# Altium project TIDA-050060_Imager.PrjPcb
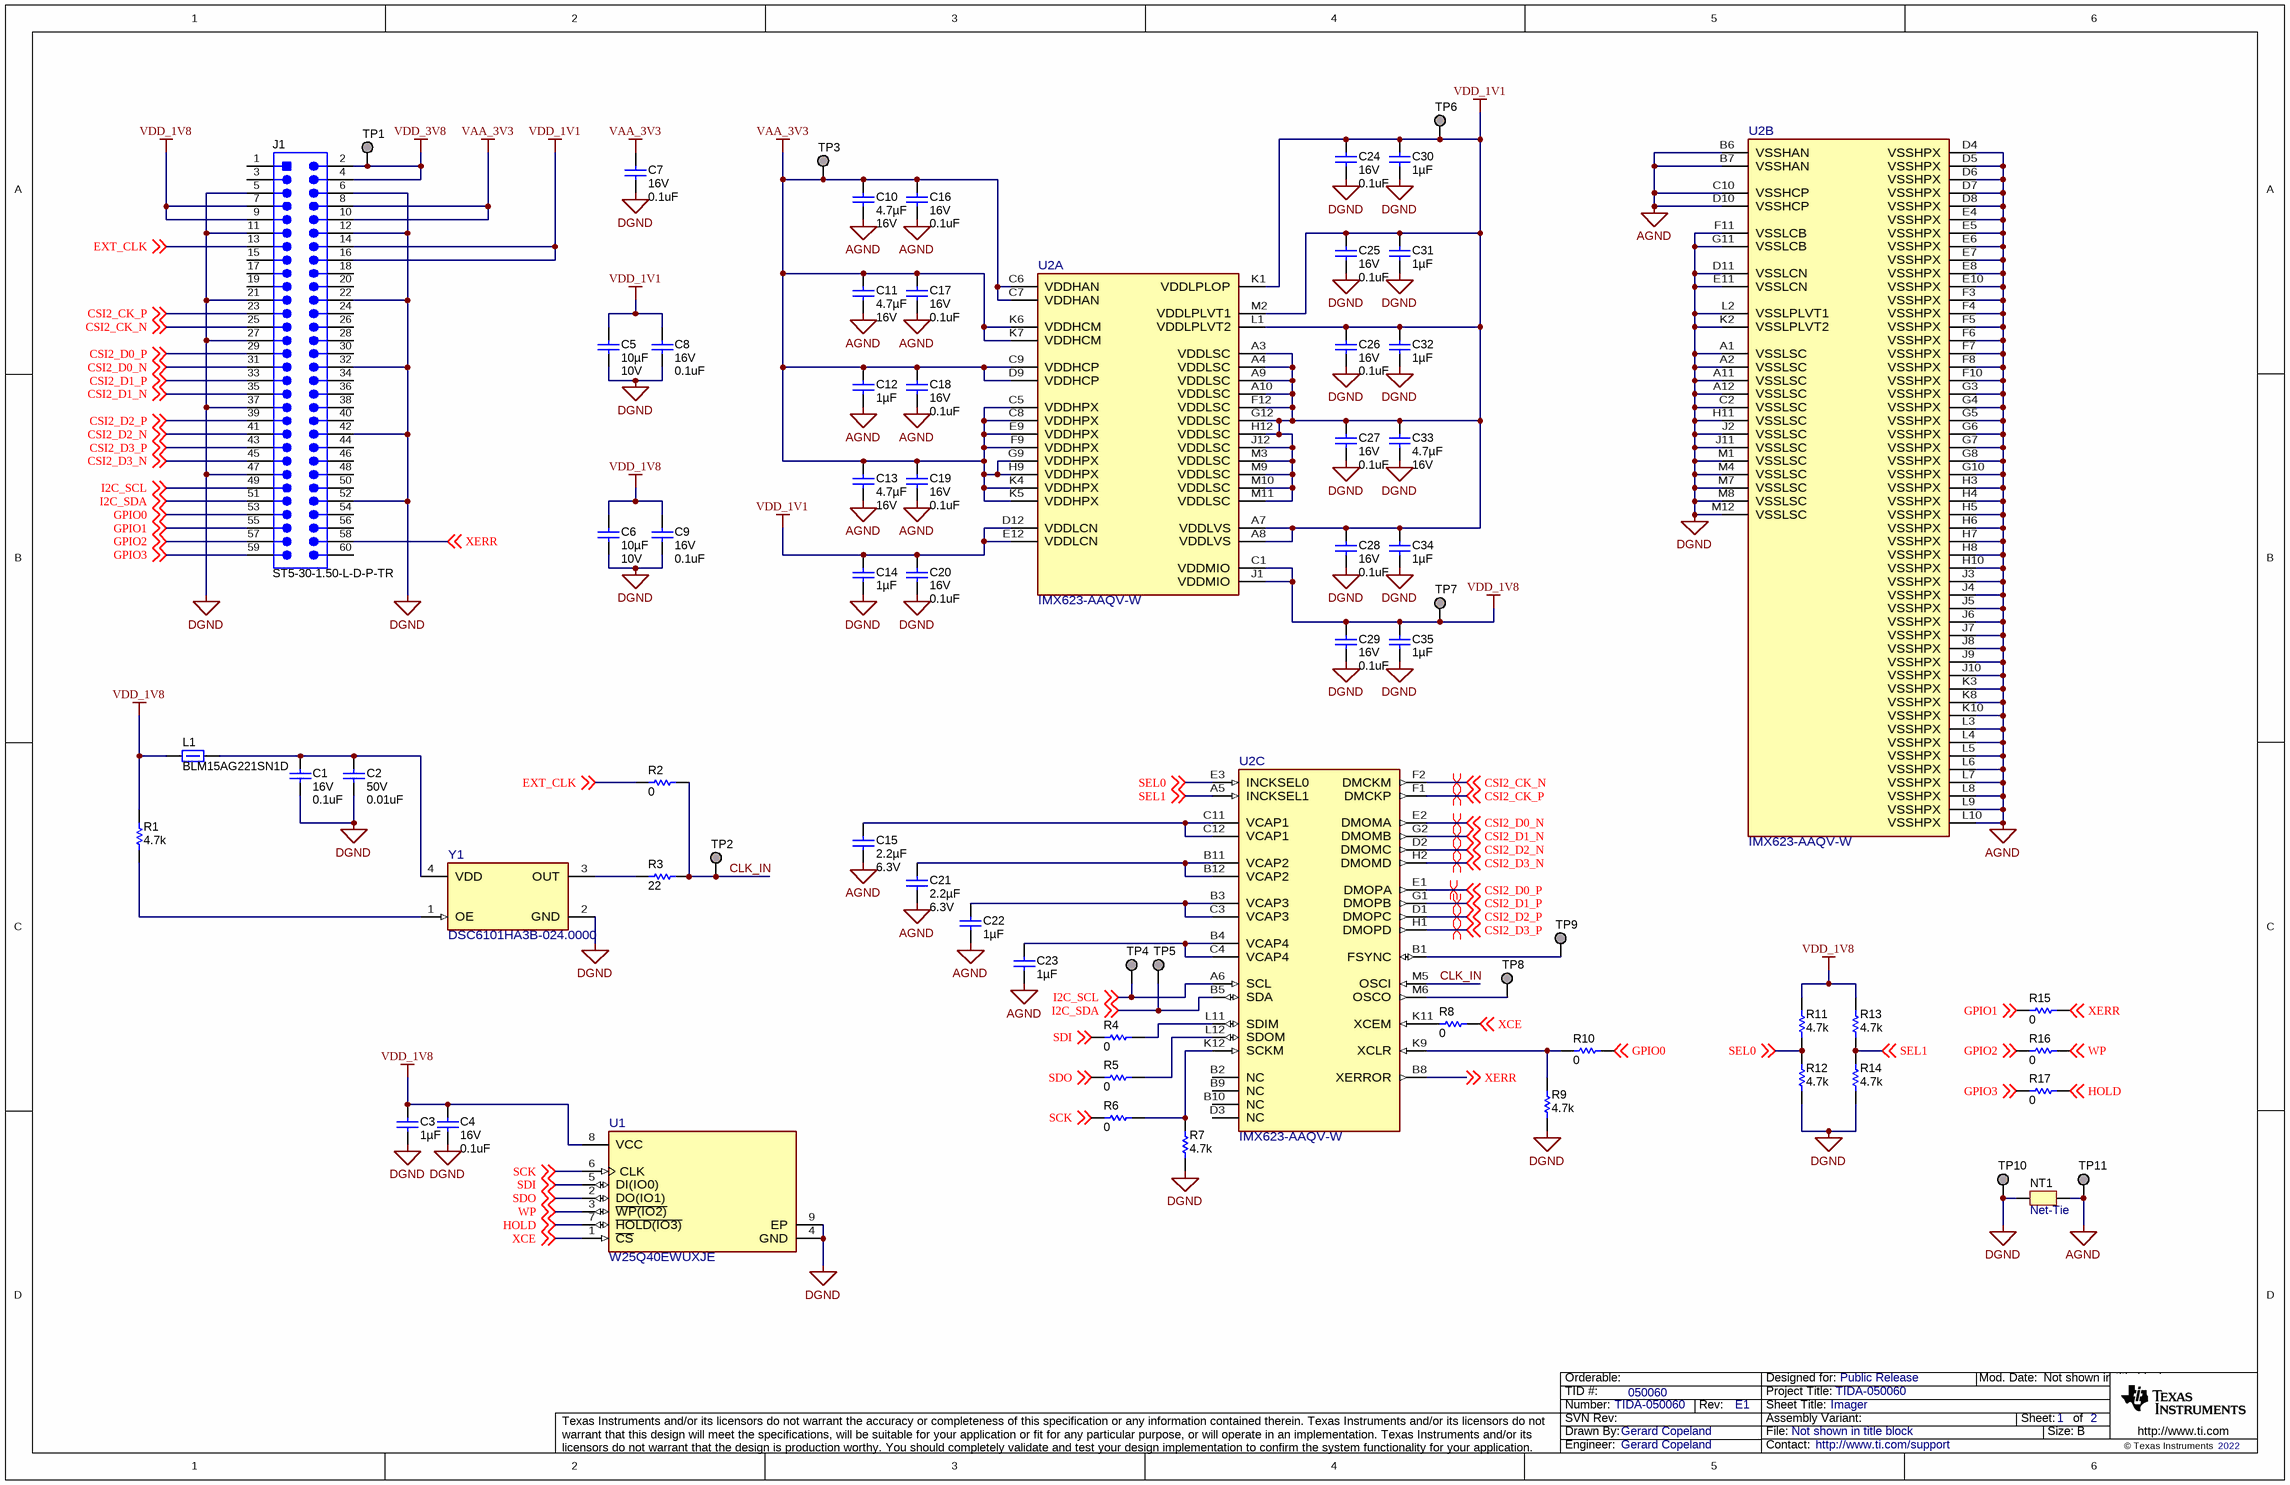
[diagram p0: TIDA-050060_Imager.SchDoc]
CopyrightYear: 2022; PCB_Layout: Gerard Copeland; PCB_Rev: E1; PRJ_Customer: Public Release; PRJ_Engineer: Gerard Copeland; PRJ_Number: TIDA-050060; PRJ_Title: TIDA-050060; SCH_Rev: E1; TechSupport: http://www.ti.com/support; TID: 050060
2 sheets, 77 parts. Net scope: global (net labels, ports and power ports of the same name join across sheets).
Board file: TIDA-050060_Imager.PcbDoc
Sheets:
  TIDA-050060_Imager.SchDoc
  TIDA-050060_Hardware.SchDoc

## Sheet TIDA-050060_Imager.SchDoc: Imager
size 431 x 279 mm; Date: Not shown in title block; ApprovedBy: Not shown in title block; CheckedBy: Not shown in title block; Author: Not shown in title block; CompanyName: Not shown in title block; DrawnBy: Gerard Copeland; Engineer: Not shown in title block; Organization: Not shown in title block; Address1: Not shown in title block; Address2: Not shown in title block; Address3: Not shown in title block; Address4: Not shown in title block; DocumentNumber: 2; Revision: Use project parameter SCH_Rev; SheetNumber: 1; SheetTotal: 2; PageSetup: Record=PageOptions¦CenterHorizontal=True¦CenterVertical=True¦PrintScale=1.00¦XCorrection=1.00¦YCorrection=1.00¦PrintKind=0¦BorderSize=5000000¦LeftOffset=0¦BottomOffset=0¦Orientation=2¦PaperLength=1000¦PaperWidth=1000¦Scale=100¦PaperSource=15¦PrintQuality=600¦MediaType=1¦DitherType=10¦PaperKind=Letter¦PrintScaleMode=1

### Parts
C1  VDC_V: 16V  ValueDisplayed: 0.1uF  [0402S]  (hidden comment: GCM155R71C104KA55D)
C2  VDC_V: 50V  ValueDisplayed: 0.01uF  [0402S]  (hidden comment: CGA2B3X7R1H103K050BB)
C3  ValueDisplayed: 1µF  [0603S]  (hidden comment: GCM188R71C105KA64J)
C4  VDC_V: 16V  ValueDisplayed: 0.1uF  [0402S]  (hidden comment: GCM155R71C104KA55D)
C5  Cap_F: 10µF  VDC_V: 10V  [0805M]  (hidden comment: GCM21BR71A106KE22L)
C6  Cap_F: 10µF  VDC_V: 10V  [0805M]  (hidden comment: GCM21BR71A106KE22L)
C7  VDC_V: 16V  ValueDisplayed: 0.1uF  [0402S]  (hidden comment: GCM155R71C104KA55D)
C8  VDC_V: 16V  ValueDisplayed: 0.1uF  [0402S]  (hidden comment: GCM155R71C104KA55D)
C9  VDC_V: 16V  ValueDisplayed: 0.1uF  [0402S]  (hidden comment: GCM155R71C104KA55D)
C10  Cap_F: 4.7µF  VDC_V: 16V  [0805M]  (hidden comment: CGA4J3X7R1C475K125AE)
C11  Cap_F: 4.7µF  VDC_V: 16V  [0805M]  (hidden comment: CGA4J3X7R1C475K125AE)
C12  ValueDisplayed: 1µF  [0603S]  (hidden comment: GCM188R71C105KA64J)
C13  Cap_F: 4.7µF  VDC_V: 16V  [0805M]  (hidden comment: CGA4J3X7R1C475K125AE)
C14  ValueDisplayed: 1µF  [0603S]  (hidden comment: GCM188R71C105KA64J)
C15  Cap_F: 2.2µF  VDC_V: 6.3V  [0603S]  (hidden comment: GCM188R70J225KE22D)
C16  VDC_V: 16V  ValueDisplayed: 0.1uF  [0402S]  (hidden comment: GCM155R71C104KA55D)
C17  VDC_V: 16V  ValueDisplayed: 0.1uF  [0402S]  (hidden comment: GCM155R71C104KA55D)
C18  VDC_V: 16V  ValueDisplayed: 0.1uF  [0402S]  (hidden comment: GCM155R71C104KA55D)
C19  VDC_V: 16V  ValueDisplayed: 0.1uF  [0402S]  (hidden comment: GCM155R71C104KA55D)
C20  VDC_V: 16V  ValueDisplayed: 0.1uF  [0402S]  (hidden comment: GCM155R71C104KA55D)
C21  Cap_F: 2.2µF  VDC_V: 6.3V  [0603S]  (hidden comment: GCM188R70J225KE22D)
C22  ValueDisplayed: 1µF  [0603S]  (hidden comment: GCM188R71C105KA64J)
C23  ValueDisplayed: 1µF  [0603S]  (hidden comment: GCM188R71C105KA64J)
C24  VDC_V: 16V  ValueDisplayed: 0.1uF  [0402S]  (hidden comment: GCM155R71C104KA55D)
C25  VDC_V: 16V  ValueDisplayed: 0.1uF  [0402S]  (hidden comment: GCM155R71C104KA55D)
C26  VDC_V: 16V  ValueDisplayed: 0.1uF  [0402S]  (hidden comment: GCM155R71C104KA55D)
C27  VDC_V: 16V  ValueDisplayed: 0.1uF  [0402S]  (hidden comment: GCM155R71C104KA55D)
C28  VDC_V: 16V  ValueDisplayed: 0.1uF  [0402S]  (hidden comment: GCM155R71C104KA55D)
C29  VDC_V: 16V  ValueDisplayed: 0.1uF  [0402S]  (hidden comment: GCM155R71C104KA55D)
C30  ValueDisplayed: 1µF  [0603S]  (hidden comment: GCM188R71C105KA64J)
C31  ValueDisplayed: 1µF  [0603S]  (hidden comment: GCM188R71C105KA64J)
C32  ValueDisplayed: 1µF  [0603S]  (hidden comment: GCM188R71C105KA64J)
C33  Cap_F: 4.7µF  VDC_V: 16V  [0805M]  (hidden comment: CGA4J3X7R1C475K125AE)
C34  ValueDisplayed: 1µF  [0603S]  (hidden comment: GCM188R71C105KA64J)
C35  ValueDisplayed: 1µF  [0603S]  (hidden comment: GCM188R71C105KA64J)
J1  ST5-30-1.50-L-D-P-TR  [Samtec_ST5-30-1_50-x-D-P]
L1  BLM15AG221SN1D  [0402S]
NT1  Net-Tie  [Net-Tie_10mil]  (net tie, no BOM)
R1  ValueDisplayed: 4.7k  [0201]  (hidden comment: RC0201JR-074K7L)
R2  ValueDisplayed: 0  [0402S]  (hidden comment: ERJ-2GE0R00X)
R3  ValueDisplayed: 22  [0402S]  (hidden comment: ERJ-2GEJ220X)
R4  ValueDisplayed: 0  [0201]  (hidden comment: ERJ-1GE0R00C)
R5  ValueDisplayed: 0  [0201]  (hidden comment: ERJ-1GE0R00C)
R6  ValueDisplayed: 0  [0201]  (hidden comment: ERJ-1GE0R00C)
R7  ValueDisplayed: 4.7k  [0201]  (hidden comment: RC0201JR-074K7L)
R8  ValueDisplayed: 0  [0201]  (hidden comment: ERJ-1GE0R00C)
R9  ValueDisplayed: 4.7k  [0201]  (hidden comment: RC0201JR-074K7L)
R10  ValueDisplayed: 0  [0201]  (hidden comment: ERJ-1GE0R00C)
R11  ValueDisplayed: 4.7k  [0201]  (hidden comment: RC0201JR-074K7L)
R12  ValueDisplayed: 4.7k  [0201]  (hidden comment: RC0201JR-074K7L)
R13  ValueDisplayed: 4.7k  [0201]  (hidden comment: RC0201JR-074K7L)
R14  ValueDisplayed: 4.7k  [0201]  (hidden comment: RC0201JR-074K7L)
R15  ValueDisplayed: 0  [0201]  (hidden comment: ERJ-1GE0R00C)
R16  ValueDisplayed: 0  [0201]  (hidden comment: ERJ-1GE0R00C)
R17  ValueDisplayed: 0  [0201]  (hidden comment: ERJ-1GE0R00C)
TP1  TP_H0.45P0.75  [TP_H045P075]  (value not drawn)  (no BOM)
TP2  TP_H0.45P0.75  [TP_H045P075]  (value not drawn)  (no BOM)
TP3  TP_H0.45P0.75  [TP_H045P075]  (value not drawn)  (no BOM)
TP4  TP_H0.45P0.75  [TP_H045P075]  (value not drawn)  (no BOM)
TP5  TP_H0.45P0.75  [TP_H045P075]  (value not drawn)  (no BOM)
TP6  TP_H0.45P0.75  [TP_H045P075]  (value not drawn)  (no BOM)
TP7  TP_H0.45P0.75  [TP_H045P075]  (value not drawn)  (no BOM)
TP8  TP_H0.45P0.75  [TP_H045P075]  (value not drawn)  (no BOM)
TP9  TP_H0.45P0.75  [TP_H045P075]  (value not drawn)  (no BOM)
TP10  TP_H0.45P0.75  [TP_H045P075]  (value not drawn)  (no BOM)
TP11  TP_H0.45P0.75  [TP_H045P075]  (value not drawn)  (no BOM)
U1  W25Q40EWUXJE  [FP-W25Q40EWUXJE_USON8-MFG]
U2  IMX623-AAQV-W  [FP-IMX623-AAQV-W_BGA144-IPC_C]  (parts A,B,C of 3)
Y1  DSC6101HA3B-024.0000  [FP-DSC6101HA3B-024.0000_VFLGA4-MFG]

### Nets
AGND: C10.2 C11.2 C12.2 C13.2 C15.2 C16.2 C17.2 C18.2 C19.2 C21.2 C22.2 C23.2 NT1.2 TP11.1 U2.B6(VSSHAN) U2.B7(VSSHAN) U2.C10(VSSHCP) U2.D4(VSSHPX) U2.D5(VSSHPX) U2.D6(VSSHPX) U2.D7(VSSHPX) U2.D8(VSSHPX) U2.D10(VSSHCP) U2.E4(VSSHPX) U2.E5(VSSHPX) U2.E6(VSSHPX) U2.E7(VSSHPX) U2.E8(VSSHPX) U2.E10(VSSHPX) U2.F3(VSSHPX) U2.F4(VSSHPX) U2.F5(VSSHPX) U2.F6(VSSHPX) U2.F7(VSSHPX) U2.F8(VSSHPX) U2.F10(VSSHPX) U2.G3(VSSHPX) U2.G4(VSSHPX) U2.G5(VSSHPX) U2.G6(VSSHPX) U2.G7(VSSHPX) U2.G8(VSSHPX) U2.G10(VSSHPX) U2.H3(VSSHPX) U2.H4(VSSHPX) U2.H5(VSSHPX) U2.H6(VSSHPX) U2.H7(VSSHPX) U2.H8(VSSHPX) U2.H10(VSSHPX) U2.J3(VSSHPX) U2.J4(VSSHPX) U2.J5(VSSHPX) U2.J6(VSSHPX) U2.J7(VSSHPX) U2.J8(VSSHPX) U2.J9(VSSHPX) U2.J10(VSSHPX) U2.K3(VSSHPX) U2.K8(VSSHPX) U2.K10(VSSHPX) U2.L3(VSSHPX) U2.L4(VSSHPX) U2.L5(VSSHPX) U2.L6(VSSHPX) U2.L7(VSSHPX) U2.L8(VSSHPX) U2.L9(VSSHPX) U2.L10(VSSHPX)
DGND: C1.2 C2.2 C3.2 C4.2 C5.2 C6.2 C7.2 C8.2 C9.2 C14.2 C20.2 C24.2 C25.2 C26.2 C27.2 C28.2 C29.2 C30.2 C31.2 C32.2 C33.2 C34.2 C35.2 J1.5 J1.6 J1.11 J1.12 J1.21 J1.22 J1.27 J1.32 J1.37 J1.42 J1.47 J1.52 NT1.1 R7.1 R9.1 R12.1 R14.1 TP10.1 U1.4(GND) U1.9(EP) U2.A1(VSSLSC) U2.A2(VSSLSC) U2.A11(VSSLSC) U2.A12(VSSLSC) U2.C2(VSSLSC) U2.D11(VSSLCN) U2.E11(VSSLCN) U2.F11(VSSLCB) U2.G11(VSSLCB) U2.H11(VSSLSC) U2.J2(VSSLSC) U2.J11(VSSLSC) U2.K2(VSSLPLVT2) U2.L2(VSSLPLVT1) U2.M1(VSSLSC) U2.M4(VSSLSC) U2.M7(VSSLSC) U2.M8(VSSLSC) U2.M12(VSSLSC) Y1.2(GND)
VAA_3V3: C7.1 C10.1 C11.1 C12.1 C13.1 C16.1 C17.1 C18.1 C19.1 J1.8 J1.10 TP3.1 U2.C5(VDDHPX) U2.C6(VDDHAN) U2.C7(VDDHAN) U2.C8(VDDHPX) U2.C9(VDDHCP) U2.D9(VDDHCP) U2.E9(VDDHPX) U2.F9(VDDHPX) U2.G9(VDDHPX) U2.H9(VDDHPX) U2.K4(VDDHPX) U2.K5(VDDHPX) U2.K6(VDDHCM) U2.K7(VDDHCM)
VDD_1V1: C5.1 C8.1 C14.1 C20.1 C24.1 C25.1 C26.1 C27.1 C28.1 C30.1 C31.1 C32.1 C33.1 C34.1 J1.14 J1.16 TP6.1 U2.A3(VDDLSC) U2.A4(VDDLSC) U2.A7(VDDLVS) U2.A8(VDDLVS) U2.A9(VDDLSC) U2.A10(VDDLSC) U2.D12(VDDLCN) U2.E12(VDDLCN) U2.F12(VDDLSC) U2.G12(VDDLSC) U2.H12(VDDLSC) U2.J12(VDDLSC) U2.K1(VDDLPLOP) U2.L1(VDDLPLVT2) U2.M2(VDDLPLVT1) U2.M3(VDDLSC) U2.M9(VDDLSC) U2.M10(VDDLSC) U2.M11(VDDLSC)
VDD_1V8: C3.1 C4.1 C6.1 C9.1 C29.1 C35.1 J1.7 J1.9 L1.1 R1.2 R11.2 R13.2 TP7.1 U1.8(VCC) U2.C1(VDDMIO) U2.J1(VDDMIO)
VDD_3V8: J1.2 J1.4 TP1.1
CLK_IN: R2.2 R3.2 TP2.1 U2.M5(OSCI)
CSI2_CK_N: J1.25 U2.F2(DMCKM) ; off-sheet CSI2_CK_N
CSI2_CK_P: J1.23 U2.F1(DMCKP) ; off-sheet CSI2_CK_P
CSI2_D0_N: J1.31 U2.E2(DMOMA) ; off-sheet CSI2_D0_N
CSI2_D0_P: J1.29 U2.E1(DMOPA) ; off-sheet CSI2_D0_P
CSI2_D1_N: J1.35 U2.G2(DMOMB) ; off-sheet CSI2_D1_N
CSI2_D1_P: J1.33 U2.G1(DMOPB) ; off-sheet CSI2_D1_P
CSI2_D2_N: J1.41 U2.D2(DMOMC) ; off-sheet CSI2_D2_N
CSI2_D2_P: J1.39 U2.D1(DMOPC) ; off-sheet CSI2_D2_P
CSI2_D3_N: J1.45 U2.H2(DMOMD) ; off-sheet CSI2_D3_N
CSI2_D3_P: J1.43 U2.H1(DMOPD) ; off-sheet CSI2_D3_P
EXT_CLK: J1.13 R2.1 ; off-sheet EXT_CLK
GPIO0: J1.53 R10.2 ; off-sheet GPIO0
GPIO1: J1.55 R15.1 ; off-sheet GPIO1
GPIO2: J1.57 R16.1 ; off-sheet GPIO2
GPIO3: J1.59 R17.1 ; off-sheet GPIO3
HOLD: R17.2 U1.7(~{HOLD(IO3)}) ; off-sheet HOLD
I2C_SCL: J1.49 TP4.1 U2.A6(SCL) ; off-sheet I2C_SCL
I2C_SDA: J1.51 TP5.1 U2.B5(SDA) ; off-sheet I2C_SDA
SCK: R6.1 U1.6(CLK) ; off-sheet SCK
SDI: R4.1 U1.5(DI(IO0)) ; off-sheet SDI
SDO: R5.1 U1.2(DO(IO1)) ; off-sheet SDO
SEL0: R11.1 R12.2 U2.E3(INCKSEL0) ; off-sheet SEL0
SEL1: R13.1 R14.2 U2.A5(INCKSEL1) ; off-sheet SEL1
WP: R16.2 U1.3(~{WP(IO2)}) ; off-sheet WP
XCE: R8.2 U1.1(~{CS}) ; off-sheet XCE
XERR: J1.58 R15.2 U2.B8(XERROR) ; off-sheet XERR
NetC1_1: C1.1 C2.1 L1.2 Y1.4(VDD)
NetC15_1: C15.1 U2.C11(VCAP1) U2.C12(VCAP1)
NetC21_1: C21.1 U2.B11(VCAP2) U2.B12(VCAP2)
NetC22_1: C22.1 U2.B3(VCAP3) U2.C3(VCAP3)
NetC23_1: C23.1 U2.B4(VCAP4) U2.C4(VCAP4)
NetR1_1: R1.1 Y1.1(OE)
NetR3_1: R3.1 Y1.3(OUT)
NetR4_2: R4.2 U2.L11(SDIM)
NetR5_2: R5.2 U2.L12(SDOM)
NetR6_2: R6.2 R7.2 U2.K12(SCKM)
NetR8_1: R8.1 U2.K11(XCEM)
NetR9_2: R9.2 R10.1 U2.K9(XCLR)
NetTP8_1: TP8.1 U2.M6(OSCO)
NetTP9_1: TP9.1 U2.B1(FSYNC)

Not connected (* = marked no-connect by the designer): J1 1 3 15 17 18 19 20 24 26 28 30 34 36 38 40 44 46 48 50 54 56 60; U2 B2(NC) B9(NC) B10(NC) D3(NC)

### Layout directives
differential pair: CSI2_CK_N, CSI2_CK_P, CSI2_D0_N, CSI2_D0_P, CSI2_D1_N, CSI2_D1_P, CSI2_D2_N, CSI2_D2_P, CSI2_D3_N, CSI2_D3_P

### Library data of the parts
C1 C4 C7-C9 C16-C20 C24-C29 = CMP-0006351-2: CAP, CERM, 0.1 uF, 16 V, +/- 10%, X7R, 0402; Manufacturer: MuRata; TaMin_C: -55°C; Polarized: N; SizeAreaWB_mm2: 3; Value1: Unknown; U/M: EA; Value: 0.1uF; TaMax_C: 125°C; SizeZ_mm: 0.6; SizeX_mm: 1; SizeY_mm: 0.5; Cap_Case: 0402; Cap_F: 100nF; AEC Category: Q200
C2 = CMP-0006324-2: CAP, CERM, 0.01 uF, 50 V, +/- 10%, X7R, AEC-Q200 Grade 1, 0402; Manufacturer: TDK; TaMin_C: -55°C; ESR_ohm: 0.333065; Polarized: N; SizeAreaWB_mm2: 3; Value1: 0.333065 ohm; U/M: EA; Value: 0.01uF; TaMax_C: 125°C; SizeZ_mm: 0.6; SizeX_mm: 1; SizeY_mm: 0.5; Cap_Case: 0402; AEC Qualified: Y; Cap_F: 10nF; IRMS_A: 323.373mA; AEC Category: Q200
C3 C12 C14 C22 C23 C30-C32 C34 C35 = CMP-0079154-1: CAP, CERM, 1 µF, 16 V,+/- 10%, X7R, AEC-Q200 Grade 1, 0603; Manufacturer: MuRata; Polarized: N; Value: 1uF; U/M: EA; VDC_V: 16V; TaMin_C: -55°C; TaMax_C: 125°C; Cap_Case: 0603; SizeArea_mm2: 1.28; SizeAreaWB_mm2: 4.68; SizeX_mm: 1.6; SizeY_mm: 0.8; SizeZ_mm: 1; AEC Category: Q200; AEC Qualified: Y
C5 C6 = CMP-0008017-2: CAP, CERM, 10 uF, 10 V, +/- 10%, X7R, 0805; Manufacturer: MuRata; TaMin_C: -55°C; Polarized: N; SizeAreaWB_mm2: 6.75; Value1: Unknown; U/M: EA; Value: 10uF; TaMax_C: 125°C; SizeZ_mm: 1.45; SizeX_mm: 2; SizeY_mm: 1.25; Cap_Case: 0805; SizeArea_mm2: 2.5; AEC Category: Q200
C10 C11 C13 C33 = CMP-0080701-1: CAP, CERM, 4.7 µF, 16 V,+/- 10%, X7R, AEC-Q200 Grade 1, 0805; Manufacturer: TDK; SizeAreaWB_mm2: 6.75; SizeArea_mm2: 2.5; AEC Qualified: Y; AEC Category: Q200; Value: 4.7uF; TaMax_C: 125°C; SizeZ_mm: 1.45; AEC Grade: 1; Polarized: N; TaMin_C: -55°C; SizeY_mm: 1.25; U/M: EA; SizeX_mm: 2; Cap_Case: 0805
C15 C21 = CMP-0007134-5: CAP, CERM, 2.2 uF, 6.3 V, +/- 10%, X7R, AEC-Q200 Grade 1, 0603; Manufacturer: MuRata; TaMin_C: -55°C; Polarized: N; SizeAreaWB_mm2: 4.68; Value1: Unknown; U/M: EA; Value: 2.2uF; TaMax_C: 125°C; SizeZ_mm: 1; SizeX_mm: 1.6; SizeY_mm: 0.8; Cap_Case: 0603; SizeArea_mm2: 1.28; AEC Qualified: Y; AEC Category: Q200
J1 = CMP-0055622-1: Header(unshrouded), 0.5mm, 30x2, Gold, SMT; Manufacturer: Samtec; CNHeader: FALSE; Current_A: 1.5A; Shrouded: N; Gender: Male; Row_Count: 2; Pitch_mm: 0.5; System: Connector
L1 = CMP-0003312-1: Ferrite Bead, 220 ohm @ 100 MHz, 0.45 A, 0402; Manufacturer: MuRata; ZTyp@100MHz_Ohm: 220; SizeAreaWB_mm2: 3; DCR_ohm: 0.29; Value1: 0.29 ohm; Value: 220 ohm; Imax_A: 450mA; SizeZ_mm: 0.6; SizeX_mm: 1; SizeY_mm: 0.5; Value2: 0.45A
NT1 = CMP-0078142-4: Single point connection between nets.
R1 R7 R9 R11-R14 = CMP-0027131-1: RES, 4.7 k, 5%, 0.05 W, 0201; Manufacturer: Yageo America; Power_W: 50mW; TempCo: 200 ppm/C; Value_Code: 4k70; U/M: EA; Value: 4.7k; EIA_Code: E24; SizeX_mm: 0.6; SizeY_mm: 0.3; SizeZ_mm: 0.26; Value2: 0.05W; SizeArea_mm2: 0.18; AEC Qualified: N; VDC_V: 25V; AEC Category: Q200
R2 = CMP-0026992-3: RES, 0, 5%, 0.1 W, AEC-Q200 Grade 0, 0402; Manufacturer: Panasonic; Power_W: 100mW; TempCo: 600 ppm/C; Value_Code: 0000; Value: 0; EIA_Code: E24; SizeX_mm: 1; SizeY_mm: 0.5; SizeZ_mm: 0.6; Value2: 0.1W; AEC Qualified: Y; VDC_V: 50V; AEC Category: Q200; SizeAreaWB_mm2: 3
R3 = CMP-0026997-2: RES, 22, 5%, 0.1 W, AEC-Q200 Grade 0, 0402; Manufacturer: Panasonic; Power_W: 100mW; TempCo: 200 ppm/C; Value_Code: 22R0; U/M: EA; Value: 22; EIA_Code: E24; SizeX_mm: 1; SizeY_mm: 0.5; SizeZ_mm: 0.6; Value2: 0.1W; AEC Qualified: Y; AEC Grade: 0; AEC Category: Q200
R4-R6 R8 R10 R15-R17 = CMP-0027011-4: RES, 0, 5%, 0.05 W, AEC-Q200 Grade 1, 0201; Manufacturer: Panasonic; Power_W: 50mW; TempCo: 600 ppm/C; Value_Code: 0000; Value: 0; EIA_Code: E24; SizeX_mm: 0.6; SizeY_mm: 0.3; SizeZ_mm: 0.26; Value2: 0.05W; SizeArea_mm2: 0.18; AEC Qualified: Y; VDC_V: 15V; AEC Category: Q200; AEC Grade: 1; SizeAreaWB_mm2: 2.08
TP1-TP11 = CMP-0003719-1: Testpoint; Manufacturer: Texas Instruments; CompType: Pad
U1 = CMP-0094008-1: W (4M-bit) Serial Flash memory, Dual/Quad SPI (XIP), USON2x3mm; Manufacturer: Winbond; Nominal Supply Current: 1-15mA; Access Time: 6ns; Memory Size: 4Mbits; SizeZ_mm: 0.6mm; Interface: SPI,Other; Max Supply Voltage: 1.95V; Standoff Height: 0mm; TaMin_C: -40°C; AEC Qualified: No; Memory Type: FLASH,NOR; TaMax_C: +105°C; Min Supply Voltage: 1.65V
U2 = CMP-0093994-1: Diagonal 7.45mm (Type 1/2.42) CMOS Solid-State Image Sensor with Square Pixel and RGGB Filter Array; Manufacturer: Sony; Min Supply Voltage: 1V; AEC Grade: Grade 2; SizeZ_mm: 1.795mm; TaMin_C: -40°C; AEC Qualified: Yes; Standoff Height: 0.27mm; Sensor Output: I2C,Other; Max Supply Voltage: 3.465V; TaMax_C: +105°C; TJmax_C: +125°C
Y1 = CMP-0093988-1: XO (Standard) CMOS Oscillator 1.71V ~ 3.63V Enable/Disable 4-VFLGA; Manufacturer: Microchip Technology; AEC Qualified: Yes; Frequency_Fixed: 24MHz; AEC Grade: Grade 1; Frequency Stability: 20ppm; SizeZ_mm: 0.89mm; TJmax_C: +150°C; Standoff Height: 0mm; Max Supply Current: 3mA

## Sheet TIDA-050060_Hardware.SchDoc
size 431 x 279 mm; Date: Not shown in title block; ApprovedBy: Not shown in title block; CheckedBy: Not shown in title block; Author: Not shown in title block; CompanyName: Not shown in title block; Engineer: Gerard Copeland; Organization: Not shown in title block; Address1: Not shown in title block; Address2: Not shown in title block; Address3: Not shown in title block; Address4: Not shown in title block; DocumentNumber: 3; Revision: Use project parameter SCH_Rev; SheetNumber: 2; SheetTotal: 2; PageSetup: Record=PageOptions¦CenterHorizontal=True¦CenterVertical=True¦PrintScale=1.00¦XCorrection=1.00¦YCorrection=1.00¦PrintKind=0¦BorderSize=5000000¦LeftOffset=0¦BottomOffset=0¦Orientation=2¦PaperLength=1000¦PaperWidth=1000¦Scale=100¦PaperSource=15¦PrintQuality=600¦MediaType=1¦DitherType=10¦PaperKind=Letter¦PrintScaleMode=1
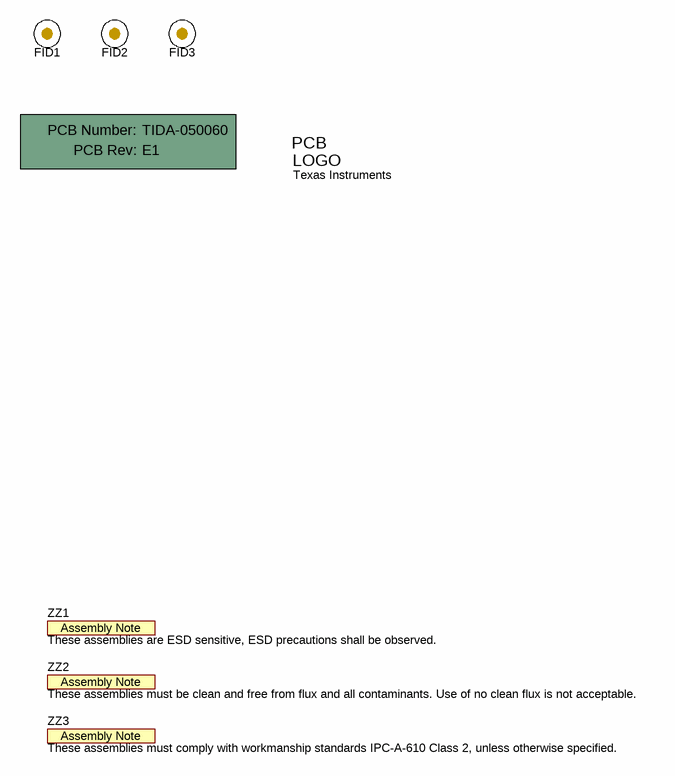
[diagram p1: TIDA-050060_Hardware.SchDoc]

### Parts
!PCB1  Printed Circuit Board  (value not drawn)  (mechanical)
FID1  Fiducial  [Fiducial10-20]  (value not drawn)
FID2  Fiducial  [Fiducial10-20]  (value not drawn)
FID3  Fiducial  [Fiducial10-20]  (value not drawn)
Logo1  Texas Instruments  [TI_Symbol_Overlay_Small]  (no BOM)
ZZ1  These assemblies are ESD sensitive, ESD precautions shall be observed.  [AssemblyNote]  (no BOM)
ZZ2  These assemblies must be clean and free from flux and all contaminants. Use of no clean flux is not acceptable.  [AssemblyNote]  (no BOM)
ZZ3  These assemblies must comply with workmanship standards IPC-A-610 Class 2, unless otherwise specified.  [AssemblyNote]  (no BOM)

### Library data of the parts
!PCB1 = CMP-0003618-2: Manufacturer: Any; PartNumber: TIDA-050060
FID1-FID3 = CMP-0077181-1: Fiducial mark.  There is nothing to buy or mount.
Logo1 = CMP-0074838-1: Texas Instrument Corporate Signature; SymbolCreator: a0412235; Lib Reference: TI_Logo; Library Reference: Logo
ZZ1 = CMP-0077236-1
ZZ2 = CMP-0077237-1
ZZ3 = CMP-0077238-1

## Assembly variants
001: not fitted FID1 FID2 FID3 R3 R4 R5 R6 R8 R11 R14 R16 R17 U1 Y1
